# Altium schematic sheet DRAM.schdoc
size 302 x 215 mm; Symbol: Sheet_A4; Device: Sheet_A4; @Project Name: blueberry; REV: 1.0; Date: 2022-11-09; Sheet: 1/1; Draw By: aixiao@aixiao.me; SheetNumber: 3; SheetTotal: 4
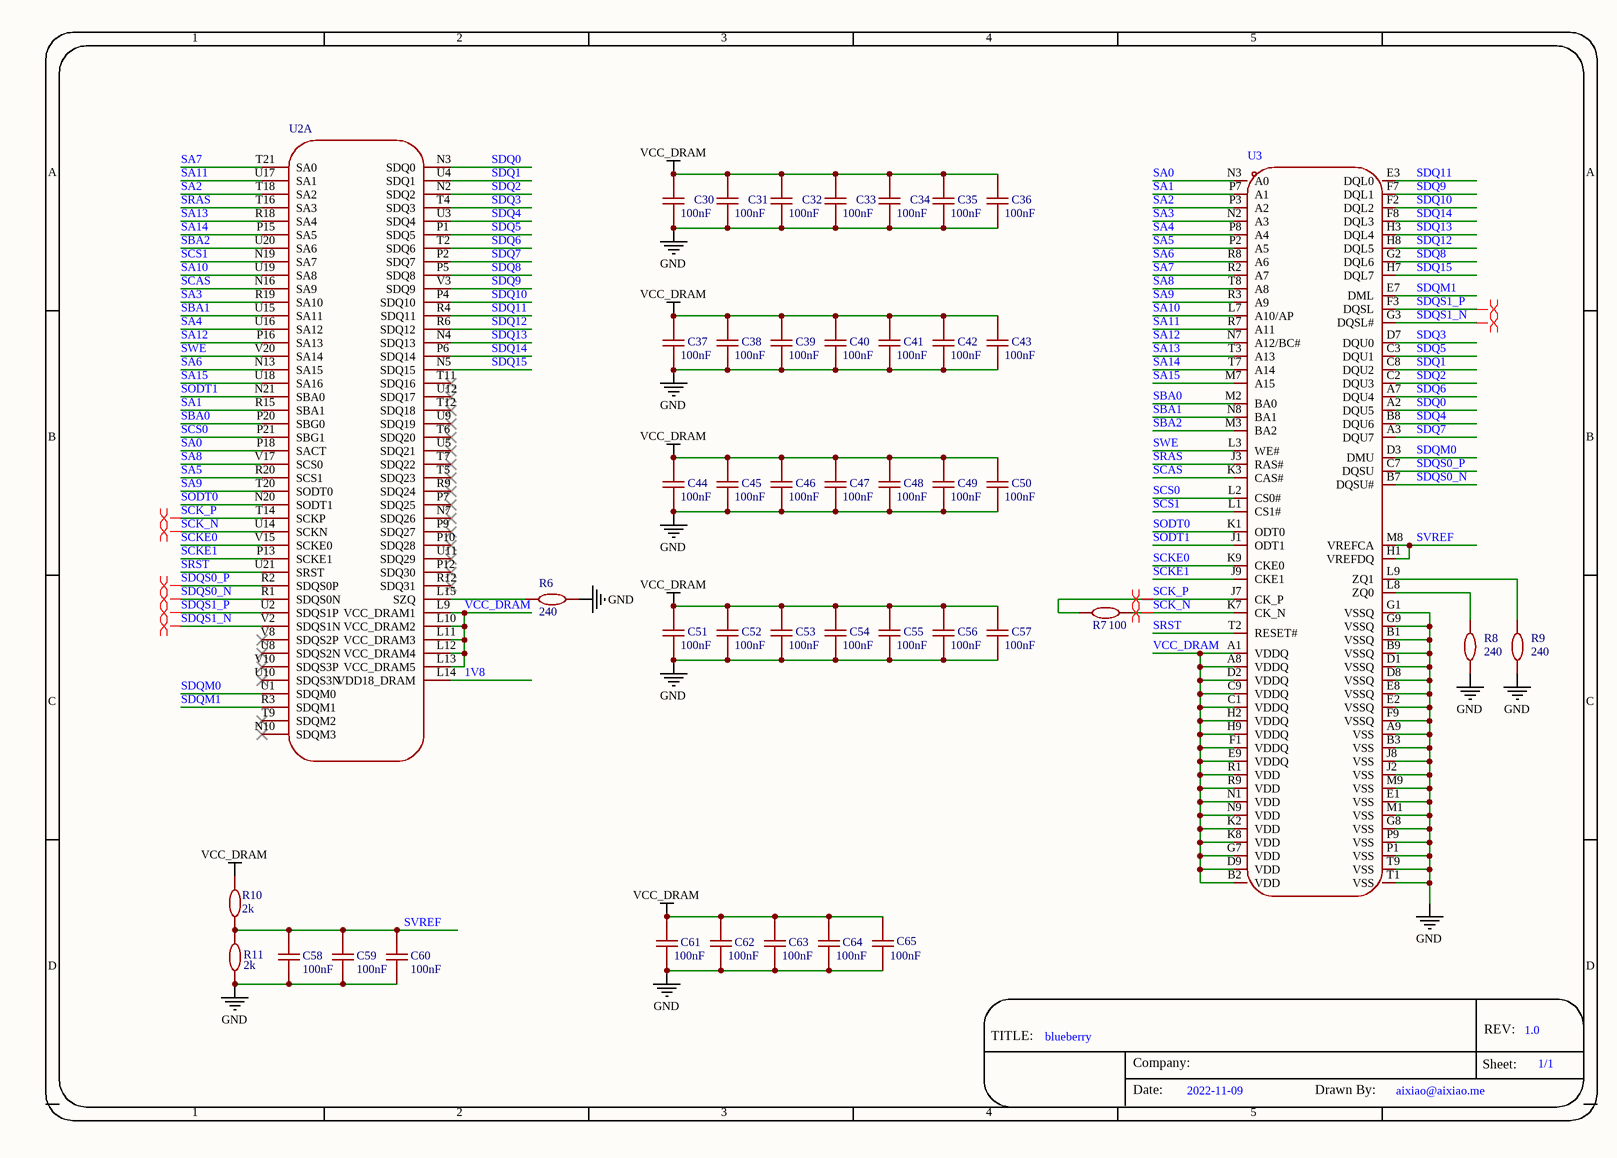
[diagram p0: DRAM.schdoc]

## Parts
C30  value 100nF  [C0402-NSK]  (hidden comment: CAP_0402)
C31  value 100nF  [C0402-NSK]  (hidden comment: CAP_0402)
C32  value 100nF  [C0402-NSK]  (hidden comment: CAP_0402)
C33  value 100nF  [C0402-NSK]  (hidden comment: CAP_0402)
C34  value 100nF  [C0402-NSK]  (hidden comment: CAP_0402)
C35  value 100nF  [C0402-NSK]  (hidden comment: CAP_0402)
C36  value 100nF  [C0402-NSK]  (hidden comment: CAP_0402)
C37  value 100nF  [C0402-NSK]  (hidden comment: CAP_0402)
C38  value 100nF  [C0402-NSK]  (hidden comment: CAP_0402)
C39  value 100nF  [C0402-NSK]  (hidden comment: CAP_0402)
C40  value 100nF  [C0402-NSK]  (hidden comment: CAP_0402)
C41  value 100nF  [C0402-NSK]  (hidden comment: CAP_0402)
C42  value 100nF  [C0402-NSK]  (hidden comment: CAP_0402)
C43  value 100nF  [C0402-NSK]  (hidden comment: CAP_0402)
C44  value 100nF  [C0402-NSK]  (hidden comment: CAP_0402)
C45  value 100nF  [C0402-NSK]  (hidden comment: CAP_0402)
C46  value 100nF  [C0402-NSK]  (hidden comment: CAP_0402)
C47  value 100nF  [C0402-NSK]  (hidden comment: CAP_0402)
C48  value 100nF  [C0402-NSK]  (hidden comment: CAP_0402)
C49  value 100nF  [C0402-NSK]  (hidden comment: CAP_0402)
C50  value 100nF  [C0402-NSK]  (hidden comment: CAP_0402)
C51  value 100nF  [C0402-NSK]  (hidden comment: CAP_0402)
C52  value 100nF  [C0402-NSK]  (hidden comment: CAP_0402)
C53  value 100nF  [C0402-NSK]  (hidden comment: CAP_0402)
C54  value 100nF  [C0402-NSK]  (hidden comment: CAP_0402)
C55  value 100nF  [C0402-NSK]  (hidden comment: CAP_0402)
C56  value 100nF  [C0402-NSK]  (hidden comment: CAP_0402)
C57  value 100nF  [C0402-NSK]  (hidden comment: CAP_0402)
C58  value 100nF  [C0402-NSK]  (hidden comment: CAP_0402)
C59  value 100nF  [C0402-NSK]  (hidden comment: CAP_0402)
C60  value 100nF  [C0402-NSK]  (hidden comment: CAP_0402)
C61  value 100nF  [C0402-NSK]  (hidden comment: CAP_0402)
C62  value 100nF  [C0402-NSK]  (hidden comment: CAP_0402)
C63  value 100nF  [C0402-NSK]  (hidden comment: CAP_0402)
C64  value 100nF  [C0402-NSK]  (hidden comment: CAP_0402)
C65  value 100nF  [C0402-NSK]  (hidden comment: CAP_0402)
R6  value 240  [R0402-NSK_2]  (hidden comment: Res_0402)
R7  value 100  [R0402-NSK_2]  (hidden comment: Res_0402)
R8  value 240  [R0402-NSK_2]  (hidden comment: Res_0402)
R9  value 240  [R0402-NSK_2]  (hidden comment: Res_0402)
R10  value 2k  [R0402-NSK_2]  (hidden comment: Res_0402)
R11  value 2k  [R0402-NSK_2]  (hidden comment: Res_0402)
U2  Allwinner_H616  [BGA284P65B1200_1400H125]  (value not drawn)  (part A of 4)
U3  H5TQ4G63EFR-RDC  [FBGA96]  (value not drawn)

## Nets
GND: C30.1 C31.1 C32.1 C33.1 C34.1 C35.1 C36.1 C37.1 C38.1 C39.1 C40.1 C41.1 C42.1 C43.1 C44.1 C45.1 C46.1 C47.1 C48.1 C49.1 C50.1 C51.1 C52.1 C53.1 C54.1 C55.1 C56.1 C57.1 C58.1 C59.1 C60.1 C61.1 C62.1 C63.1 C64.1 C65.1 R6.2 R8.1 R9.1 R11.1 U3.A9(VSS) U3.B1(VSSQ) U3.B3(VSS) U3.B9(VSSQ) U3.D1(VSSQ) U3.D8(VSSQ) U3.E1(VSS) U3.E2(VSSQ) U3.E8(VSSQ) U3.F9(VSSQ) U3.G1(VSSQ) U3.G8(VSS) U3.G9(VSSQ) U3.J2(VSS) U3.J8(VSS) U3.M1(VSS) U3.M9(VSS) U3.P1(VSS) U3.P9(VSS) U3.T1(VSS) U3.T9(VSS)
VCC_DRAM: C30.2 C31.2 C32.2 C33.2 C34.2 C35.2 C36.2 C37.2 C38.2 C39.2 C40.2 C41.2 C42.2 C43.2 C44.2 C45.2 C46.2 C47.2 C48.2 C49.2 C50.2 C51.2 C52.2 C53.2 C54.2 C55.2 C56.2 C57.2 C61.2 C62.2 C63.2 C64.2 C65.2 R10.2 U2.L9(VCC_DRAM1) U2.L10(VCC_DRAM2) U2.L11(VCC_DRAM3) U2.L12(VCC_DRAM4) U2.L13(VCC_DRAM5) U3.A1(VDDQ) U3.A8(VDDQ) U3.B2(VDD) U3.C1(VDDQ) U3.C9(VDDQ) U3.D2(VDDQ) U3.D9(VDD) U3.E9(VDDQ) U3.F1(VDDQ) U3.G7(VDD) U3.H2(VDDQ) U3.H9(VDDQ) U3.K2(VDD) U3.K8(VDD) U3.N1(VDD) U3.N9(VDD) U3.R1(VDD) U3.R9(VDD)
1V8: U2.L14(VDD18_DRAM)
SA0: U2.P18(SACT) U3.N3(A0)
SA1: U2.R15(SBA1) U3.P7(A1)
SA2: U2.T18(SA2) U3.P3(A2)
SA3: U2.R19(SA10) U3.N2(A3)
SA4: U2.U16(SA12) U3.P8(A4)
SA5: U2.R20(SCS1) U3.P2(A5)
SA6: U2.N13(SA15) U3.R8(A6)
SA7: U2.T21(SA0) U3.R2(A7)
SA8: U2.V17(SCS0) U3.T8(A8)
SA9: U2.T20(SODT0) U3.R3(A9)
SA10: U2.U19(SA8) U3.L7(A10/AP)
SA11: U2.U17(SA1) U3.R7(A11)
SA12: U2.P16(SA13) U3.N7(A12/BC#)
SA13: U2.R18(SA4) U3.T3(A13)
SA14: U2.P15(SA5) U3.T7(A14)
SA15: U2.U18(SA16) U3.M7(A15)
SBA0: U2.P20(SBG0) U3.M2(BA0)
SBA1: U2.U15(SA11) U3.N8(BA1)
SBA2: U2.U20(SA6) U3.M3(BA2)
SCAS: U2.N16(SA9) U3.K3(CAS#)
SCK_N: R7.2 U2.U14(SCKN) U3.K7(CK_N)
SCK_P: R7.1 U2.T14(SCKP) U3.J7(CK_P)
SCKE0: U2.V15(SCKE0) U3.K9(CKE0)
SCKE1: U2.P13(SCKE1) U3.J9(CKE1)
SCS0: U2.P21(SBG1) U3.L2(CS0#)
SCS1: U2.N19(SA7) U3.L1(CS1#)
SDQ0: U2.N3(SDQ0) U3.A2(DQU5)
SDQ1: U2.U4(SDQ1) U3.C8(DQU2)
SDQ2: U2.N2(SDQ2) U3.C2(DQU3)
SDQ3: U2.T4(SDQ3) U3.D7(DQU0)
SDQ4: U2.U3(SDQ4) U3.B8(DQU6)
SDQ5: U2.P1(SDQ5) U3.C3(DQU1)
SDQ6: U2.T2(SDQ6) U3.A7(DQU4)
SDQ7: U2.P2(SDQ7) U3.A3(DQU7)
SDQ8: U2.P5(SDQ8) U3.G2(DQL6)
SDQ9: U2.V3(SDQ9) U3.F7(DQL1)
SDQ10: U2.P4(SDQ10) U3.F2(DQL2)
SDQ11: U2.R4(SDQ11) U3.E3(DQL0)
SDQ12: U2.R6(SDQ12) U3.H8(DQL5)
SDQ13: U2.N4(SDQ13) U3.H3(DQL4)
SDQ14: U2.P6(SDQ14) U3.F8(DQL3)
SDQ15: U2.N5(SDQ15) U3.H7(DQL7)
SDQM0: U2.U1(SDQM0) U3.D3(DMU)
SDQM1: U2.R3(SDQM1) U3.E7(DML)
SDQS0_N: U2.R1(SDQS0N) U3.B7(DQSU#)
SDQS0_P: U2.R2(SDQS0P) U3.C7(DQSU)
SDQS1_N: U2.V2(SDQS1N) U3.G3(DQSL#)
SDQS1_P: U2.U2(SDQS1P) U3.F3(DQSL)
SODT0: U2.N20(SODT1) U3.K1(ODT0)
SODT1: U2.N21(SBA0) U3.J1(ODT1)
SRAS: U2.T16(SA3) U3.J3(RAS#)
SRST: U2.U21(SRST) U3.T2(RESET#)
SVREF: C58.2 C59.2 C60.2 R10.1 R11.2 U3.H1(VREFDQ) U3.M8(VREFCA)
SWE: U2.V20(SA14) U3.L3(WE#)
NetR6_1: R6.1 U2.L15(SZQ)
NetR8_2: R8.2 U3.L8(ZQ0)
NetR9_2: R9.2 U3.L9(ZQ1)

Not connected (* = marked no-connect by the designer): U2 N7(SDQ26)* N10(SDQM3)* P7(SDQ25)* P9(SDQ27)* P10(SDQ28)* P12(SDQ30)* R9(SDQ24)* R12(SDQ31)* T5(SDQ23)* T6(SDQ20)* T7(SDQ22)* T9(SDQM2)* T11(SDQ16)* T12(SDQ18)* U5(SDQ21)* U8(SDQS2N)* U9(SDQ19)* U10(SDQS3N)* U11(SDQ29)* U12(SDQ17)* V8(SDQS2P)* V10(SDQS3P)*

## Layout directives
differential pair: SCK_N, SCK_P, SDQS0_N, SDQS0_P, SDQS1_N, SDQS1_P

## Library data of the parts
C30-C65 = CAP_0402: Symbol: C1210X7R475K630NT; Convert to PCB: yes
R6-R11 = Res_0402: Symbol: 电阻; Convert to PCB: yes
U2 = Allwinner_H616: Symbol: H616-BGA-190823; Convert to PCB: yes
U3 = H5TQ4G63EFR-RDC: Manufacturer: HYNIX(海力士); Pin Type: IN; Add into BOM: yes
